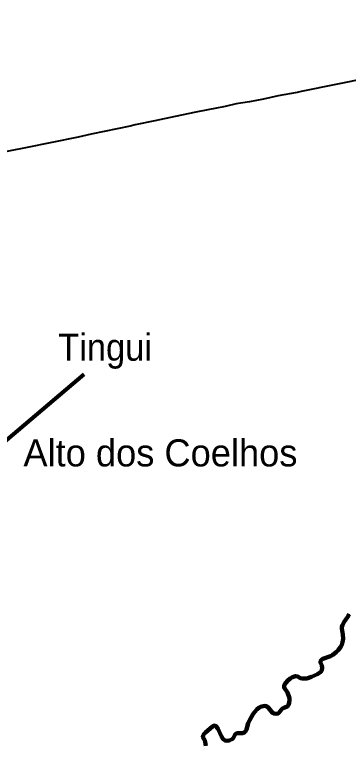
# Model space of a CAD drawing. Extents: x 553962 to 842807, y 8883888 to 9032388.
# Drawn here: x 619995 to 626151, y 8959925 to 8973416 of the extents above; entities that cross this region are included whole.
import ezdxf

# ---------------------------------------------------------------- set-up
doc = ezdxf.new("R2010")
doc.units = 0
doc.header["$LTSCALE"] = 200
for name, color, linetype, lineweight in [('12', 7, 'Continuous', 25), ('24', 7, 'Continuous', 25), ('28', 7, 'Continuous', 40), ('41', 7, 'Continuous', 40), ('9', 7, 'Continuous', 90)]:
    doc.layers.add(name, color=color, linetype=linetype, lineweight=lineweight)

msp = doc.modelspace()

# ---------------------------------------------------------------- linework, layer by layer
at = {"layer": '12', "lineweight": 40}
for points in [[(627892.1, 8972517.3), (627787.3, 8972497.2), (626527.3, 8972247.8), (625278.3, 8971995.4), (625208.3, 8971975.3), (624859.1, 8971919.6), (624586.2, 8971856.1), (624327.1, 8971807.6), (624078.9, 8971766.2), (623877.2, 8971718.8), (623688.2, 8971682.4)], [(623749, 8971693.5), (623336.6, 8971616.7), (622957.2, 8971536), (622583.2, 8971453.3), (622220.1, 8971379.6), (622127, 8971357.4)], [(622127, 8971357.4), (621646.3, 8971257.5), (621405.3, 8971207.1)], [(621405.3, 8971207.1), (621164.3, 8971156.6), (620679.5, 8971055.7), (620194.7, 8970957.7), (619622.5, 8970843.7), (619047.4, 8970728.6), (618626.9, 8970634.8), (618210.5, 8970553), (617794.1, 8970471.2), (617379.1, 8970389.4), (616970.9, 8970302.6), (616723.1, 8970254.2)]]:
    msp.add_lwpolyline(points, dxfattribs=at)
at = {"layer": '24'}
for points in [[(626164.1, 8962350.8), (626134.9, 8962291.6), (626076.5, 8962209.4), (626043, 8962145.2), (626033.4, 8962116.2), (626031, 8962086.1), (626050.8, 8961971), (626052.2, 8961893.9), (626043.5, 8961829.8), (626030, 8961782.7), (626007.6, 8961741.6), (625960.4, 8961681.4), (625923.5, 8961643.3), (625862.9, 8961595.1), (625822.7, 8961574), (625681.1, 8961524.7), (625666.2, 8961515.7), (625650, 8961497.6), (625640, 8961477.6), (625636.3, 8961455.5), (625664.5, 8961397.5), (625669.9, 8961359.4), (625663.1, 8961316.3), (625644, 8961283.3), (625582.5, 8961243.1), (625473.5, 8961191.8)], [(625473.5, 8961191.8), (625385.3, 8961162.7), (625335.4, 8961158.6), (625297, 8961160.5), (625268.2, 8961168.5), (625214.1, 8961198.5), (625173.4, 8961205.4), (625117.9, 8961186.3), (625078.9, 8961163.2), (625027.5, 8961119), (625000.9, 8961089), (624975.3, 8961048.8), (624966.1, 8961016.8), (624966.2, 8960999.8), (624973, 8960982.7), (625029.9, 8960900.7), (625064.6, 8960798.6), (625067, 8960768.6), (625061.1, 8960709.5), (625046, 8960671.4), (625027.5, 8960644.3), (625011.3, 8960634.2), (624961, 8960619.2), (624936.3, 8960606.1), (624912, 8960582), (624879.5, 8960536.9), (624854.3, 8960516.8), (624811.3, 8960509.7), (624784.5, 8960512.7), (624750.7, 8960527.7), (624725.6, 8960556.7), (624680, 8960618.7), (624640.1, 8960648.7), (624615.7, 8960653.7), (624577.3, 8960648.6), (624531.2, 8960635.5), (624496.8, 8960619.4)], [(624496.8, 8960619.4), (624466.5, 8960595.3), (624466.5, 8960595.3), (624418.2, 8960536.2), (624388.4, 8960493.1), (624334.1, 8960398.8), (624304.9, 8960334.7), (624271.6, 8960219.4), (624255.9, 8960184.4), (624237, 8960167.3), (624209.4, 8960152.2), (624177.8, 8960149.2), (624105.6, 8960150.1), (624084, 8960144), (624056.4, 8960117.9), (624029.7, 8960062.8), (624008.5, 8960040.7), (623952.6, 8960017.6), (623906.6, 8960011.5), (623879.7, 8960018.5), (623839.9, 8960041.5), (623809.1, 8960087.5), (623742.1, 8960236.6), (623708.6, 8960280.6), (623691, 8960291.6), (623663.5, 8960287.6), (623642.3, 8960274.5), (623518.1, 8960166.2), (623487.9, 8960132.1), (623473.9, 8960107), (623469.3, 8960080), (623503, 8960016.9), (623511.8, 8959991.9), (623518.8, 8959918.8)]]:
    msp.add_lwpolyline(points, dxfattribs=at)
at = {"layer": '28', "lineweight": 80}
msp.add_lwpolyline([(612196.3, 8961548), (619517.6, 8965291.5), (621276.7, 8966775.5)], dxfattribs=at)
at = {"layer": '9'}
for points in [[(626164.1, 8962350.8), (626134.9, 8962291.6), (626076.5, 8962209.4), (626043, 8962145.2), (626033.4, 8962116.2), (626031, 8962086.1), (626050.8, 8961971), (626052.2, 8961893.9), (626043.5, 8961829.8), (626030, 8961782.7), (626007.6, 8961741.6), (625960.4, 8961681.4), (625923.5, 8961643.3), (625862.9, 8961595.1), (625822.7, 8961574), (625681.1, 8961524.7), (625666.2, 8961515.7), (625650, 8961497.6), (625640, 8961477.6), (625636.3, 8961455.5), (625664.5, 8961397.5), (625669.9, 8961359.4), (625663.1, 8961316.3), (625644, 8961283.3), (625582.5, 8961243.1), (625473.5, 8961191.8)], [(625473.5, 8961191.8), (625385.3, 8961162.7), (625335.4, 8961158.6), (625297, 8961160.5), (625268.2, 8961168.5), (625214.1, 8961198.5), (625173.4, 8961205.4), (625117.9, 8961186.3), (625078.9, 8961163.2), (625027.5, 8961119), (625000.9, 8961089), (624975.3, 8961048.8), (624966.1, 8961016.8), (624966.2, 8960999.8), (624973, 8960982.7), (625029.9, 8960900.7), (625064.6, 8960798.6), (625067, 8960768.6), (625061.1, 8960709.5), (625046, 8960671.4), (625027.5, 8960644.3), (625011.3, 8960634.2), (624961, 8960619.2), (624936.3, 8960606.1), (624912, 8960582), (624879.5, 8960536.9), (624854.3, 8960516.8), (624811.3, 8960509.7), (624784.5, 8960512.7), (624750.7, 8960527.7), (624725.6, 8960556.7), (624680, 8960618.7), (624640.1, 8960648.7), (624615.7, 8960653.7), (624577.3, 8960648.6), (624531.2, 8960635.5), (624496.8, 8960619.4)], [(624496.8, 8960619.4), (624466.5, 8960595.3), (624466.5, 8960595.3), (624418.2, 8960536.2), (624388.4, 8960493.1), (624334.1, 8960398.8), (624304.9, 8960334.7), (624271.6, 8960219.4), (624255.9, 8960184.4), (624237, 8960167.3), (624209.4, 8960152.2), (624177.8, 8960149.2), (624105.6, 8960150.1), (624084, 8960144), (624056.4, 8960117.9), (624029.7, 8960062.8), (624008.5, 8960040.7), (623952.6, 8960017.6), (623906.6, 8960011.5), (623879.7, 8960018.5), (623839.9, 8960041.5), (623809.1, 8960087.5), (623742.1, 8960236.6), (623708.6, 8960280.6), (623691, 8960291.6), (623663.5, 8960287.6), (623642.3, 8960274.5), (623518.1, 8960166.2), (623487.9, 8960132.1), (623473.9, 8960107), (623469.3, 8960080), (623503, 8960016.9), (623511.8, 8959991.9), (623518.8, 8959918.8)]]:
    msp.add_lwpolyline(points, dxfattribs=at)
msp.add_spline([(592698.5, 8977198.4), (599903.5, 8973292.7), (608459.2, 8968138.2), (612674.8, 8965332.6), (616842, 8962096.4), (620005, 8958671.2), (621134, 8957974.7), (621473.4, 8956805.3), (621586.2, 8956597.5)], degree=3, dxfattribs=at)

# ---------------------------------------------------------------- texts
at = {"layer": '41', "width": 0.95}
msp.add_text('Tingui', height=500, dxfattribs=at).set_placement((620798.3, 8967026.8))
at = {"layer": '41'}
msp.add_text('Alto dos Coelhos', height=500, dxfattribs=at).set_placement((620156.6, 8965075.6))

doc.saveas('drawing.dxf')
